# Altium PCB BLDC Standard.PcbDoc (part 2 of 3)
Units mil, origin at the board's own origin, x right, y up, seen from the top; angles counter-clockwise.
Board outline 4950 x 3000 mil, 4 copper layers (Top Layer, MidLayer1, MidLayer2, Bottom Layer), stack 63.4 mil thick; 211 components, 117 nets, 576 pads, 1027 vias.
Unrouted connection lines stored in the file: 2.
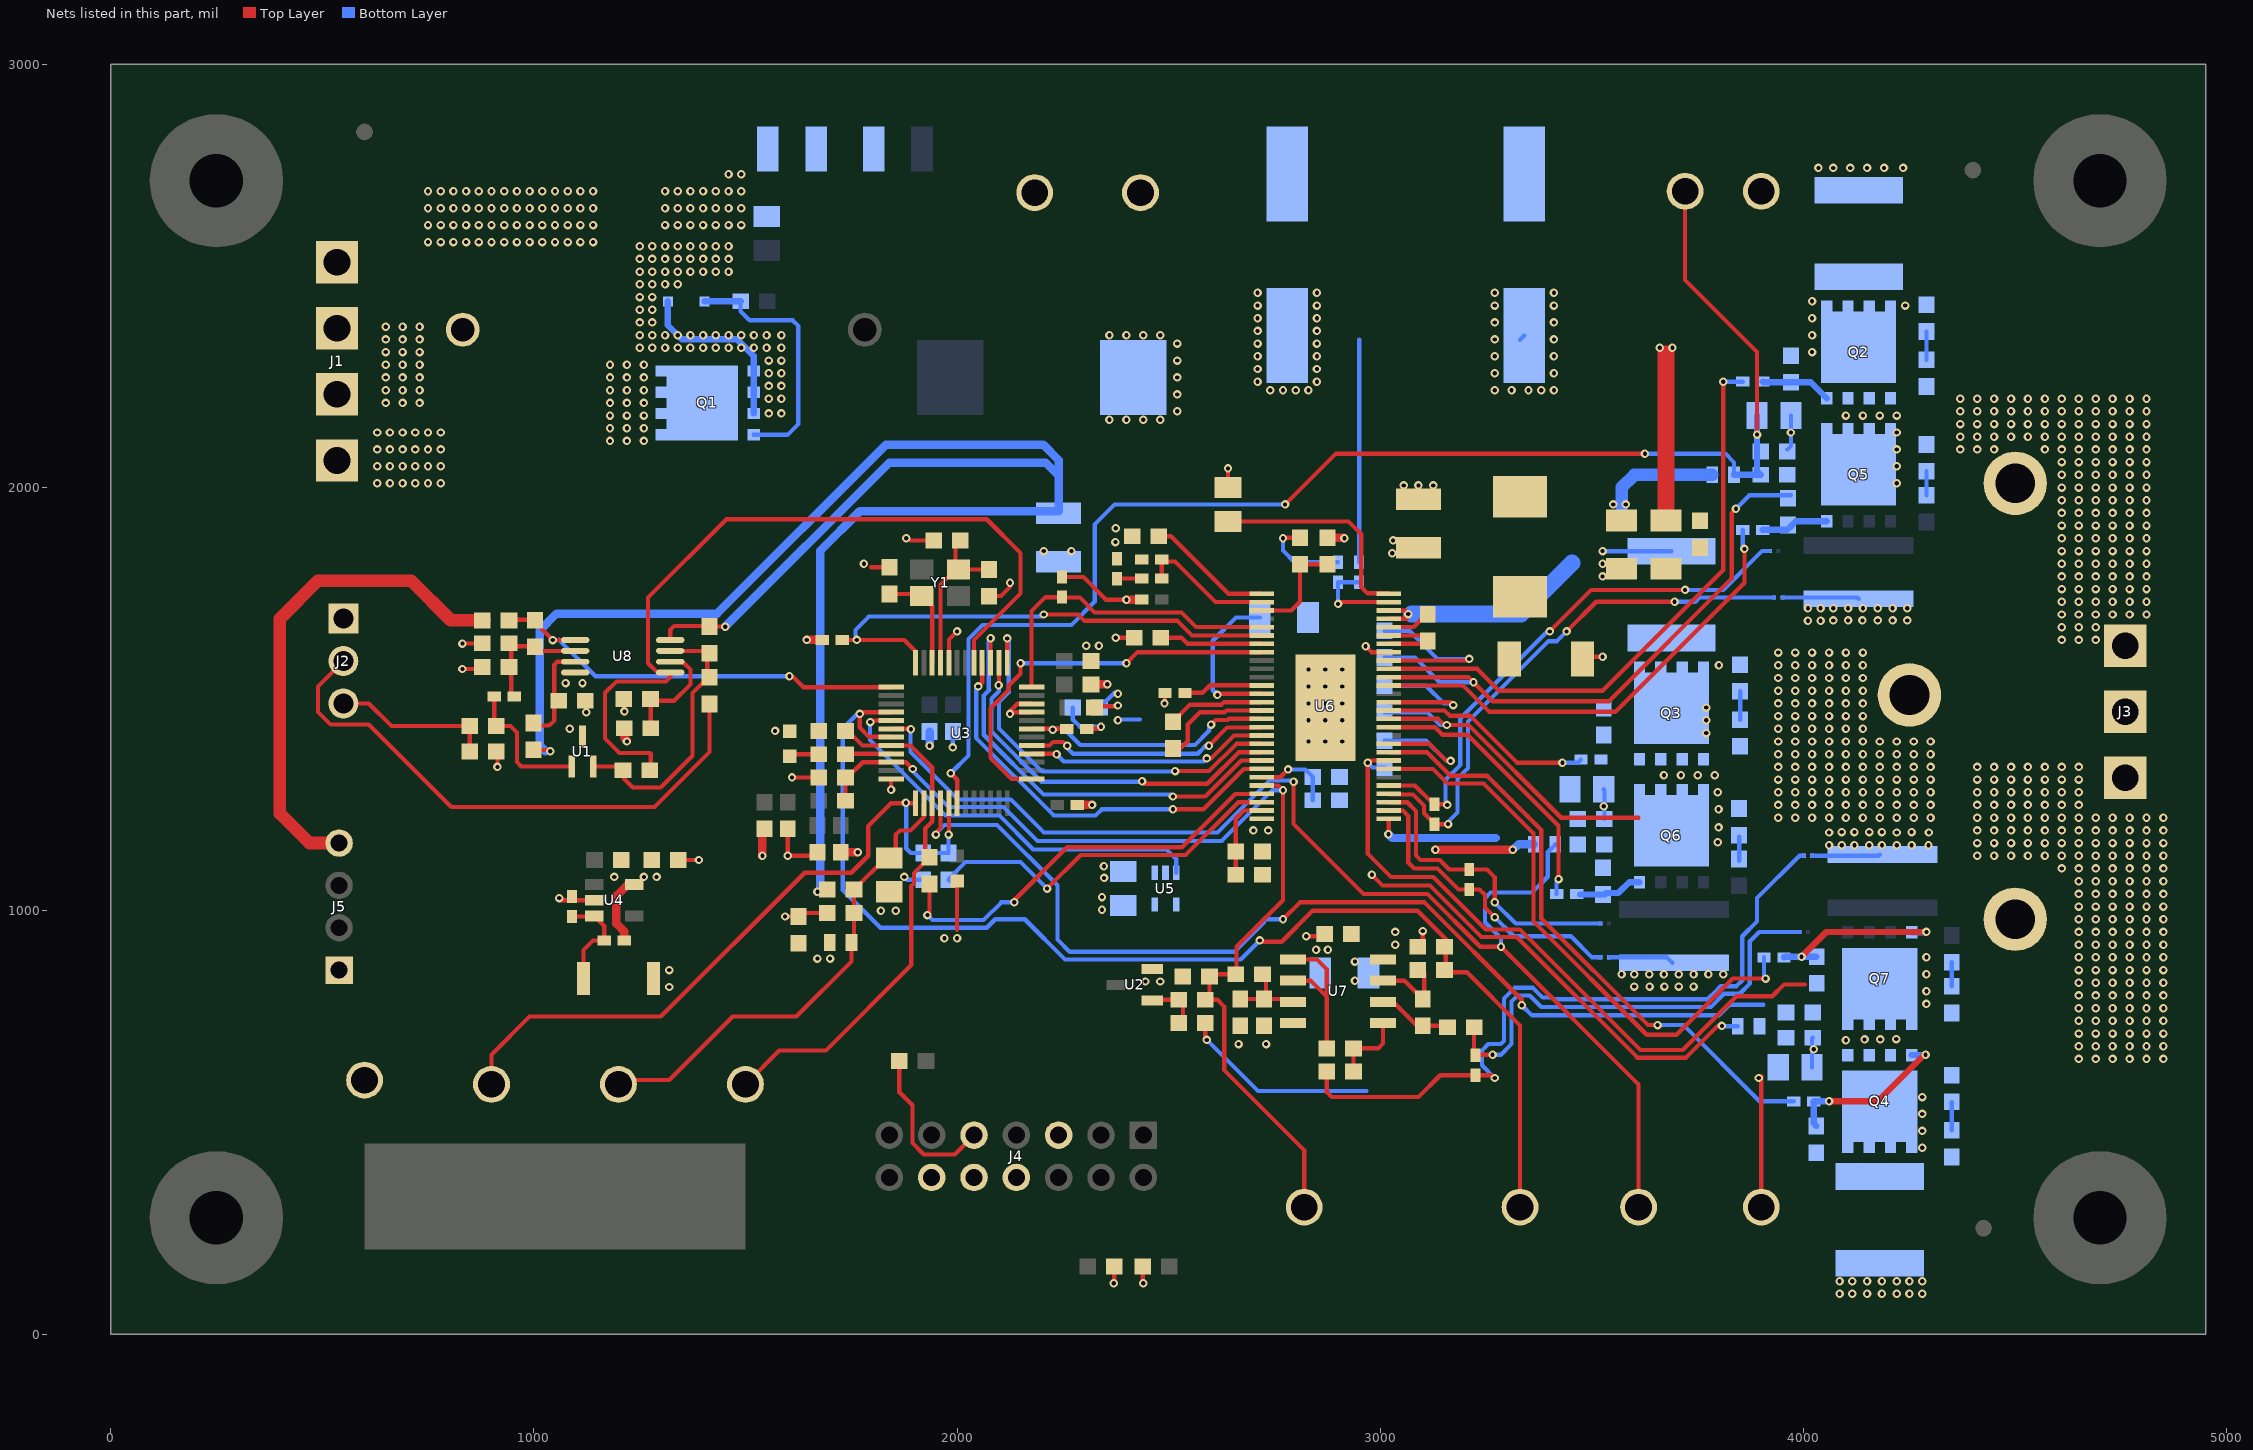
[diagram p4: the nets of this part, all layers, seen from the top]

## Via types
v1: diameter 20, hole 10, Top Layer to Bottom Layer, 1027 vias

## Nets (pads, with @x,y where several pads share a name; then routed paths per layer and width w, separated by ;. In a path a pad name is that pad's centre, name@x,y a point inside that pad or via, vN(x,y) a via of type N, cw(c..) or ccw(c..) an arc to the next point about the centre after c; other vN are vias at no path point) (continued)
3P3V: C30.2 C36.1 C38.1 C45.1 C46.1 C61.2 D2.1 D3.1 D4.1 D5.1 J4.5 J5.4 L2.1 L3.1 L4.1 L5.1 L7.2 R2.2 R12.2 R45.2 R47.2 R52.1 R53.2 R54.1 R58.2 R59.1 U4.5 U5.4 U5.5 U6.49 U7.8 | length 3510.6
  Top Layer w10: R52.1@2248,1788.62 2298.38,1788.62 2352,1735 v1(2400,1735) ; v1(2965,1625) 2978.89,1611.11 U6.49@3019.92,1611.11 ; v1(2980,1085) 3005,1060 3117,1060 3239,938 3322.09,938 3607.09,653 3721.89,653 3796.89,728 v1(3807,728)
  Top Layer w20: R12.2@1213.5,1431.3 1213.5,1409.5 v1@1220,1403 ; R47.2@1213.62,930 1213.62,951.38 1208.2,956.8 1208.13,956.8 1195,969.94 1195,1035.16 1222.24,1062.4 U4.5@1237.24,1062.4 ; v1(1540,1130) L2.1@1540,1178.5 ; v1(1645,1640) R54.1@1681.38,1640 ; L5.1@1725,1138.5 v1(1765.5,1138.5) ; R59.1@2283.62,1250 v1@2315,1250 ; L4.1@2316.5,1535 v1(2355,1535) ; v1(2400,1735) R58.2@2436.38,1735 ; R53.2@2875,1881.5 2913.5,1881.5 v1(2915,1880) ; v1(3130,1144) v1(3312.63,1144)
  Top Layer w30: J5.4@540,1160 470,1160 400,1230 400,1690 490,1780 710,1780 803.7,1686.3 R2.2@883.5,1686.3
  Bottom Layer w10: v1(3807,728) 3808,727 D4.1@3844.41,727
  Bottom Layer w20: v1(1935,1390) L3.1@1935,1423.5 ; v1(3312.63,1144) 3326.94,1157 ; 3326.97,1156.97 D3.1@3362.2,1156.97
  Bottom Layer w30: 3570,1955 3570,2000 3600,2030 D2.1@3784.41,2030
  other v1: 1670,887 1700,887 3035,920 3035,950 2342.32,1002.56 2342.32,1032.56 1190,1080 1260,1080 1290,1080 2319,1250 1220,1400 3028.28,1845 3030,1875 3550,1960 3580,1960
A_H_ISENSE: C64.1 NT1.2 U6.33 | length 1257.8
  Top Layer w10: U6.33@3019.92,1295.91 3081.37,1295.91 C64.1@3123,1254.28 ; C64.1@3123,1251.62 3123,1251 3126.46,1251 C64.1@3129,1253.54 ; C64.1@3129,1251.62 3153.38,1251.62 v1@3155,1250 ; v1(3400,1660) 3498,1758 v1(3720,1758)
  Bottom Layer w10: v1@3154,1250 3154,1309.46 3189,1344.46 3189,1454.81 3390.64,1656.46 ; v1(3720,1758) 3810,1758 3902,1850 NT1.2@3920,1850
  other v1: 3158,1250
A_I_ADC: C60.1 R63.2 TP10.1 U3.8 U3.15 | length 1250.5
  Top Layer w10: TP10.1@1500,590 1580,670 1690,670 1891.85,871.85 1891.85,1058.18 1898,1064.33 1898,1089.5 R63.2@1925,1116.5 ; C60.1@1736.5,1425 1742,1425 1776.5,1390.5 U3.8@1844.1,1390.5 1889.5,1390.5 1941.2,1338.8 U3.15@1941.2,1254 1941.2,1211.2 1925,1195 R63.2@1925,1116.5 ; R63.2@1935,1126.5 R63.2@1925,1116.5
A_L_ISENSE: C64.2 NT4.2 U6.32 | length 1283.8
  Top Layer w10: U6.32@3019.92,1276.21 3021.12,1275.01 3076.81,1275.01 3103,1248.82 3103,1230.38 3129,1204.38 3154.38,1204.38 v1@3155,1205 ; v1(3440,1660) 3510,1730 v1(3695,1730)
  Bottom Layer w10: v1@3155,1205 3182,1232 3182,1312 3207,1337 3207,1447 3397,1637 3417,1637 v1(3440,1660) ; v1(3695,1730) 3744,1730 3754,1740 NT4.2@3930,1740
  other v1: 3160,1205
A_PHASE: C14.2 C20.1 C47.2 J3.1 PTH-A.1 Q2.1 Q2.2 Q2.3 Q5.5 Q5.6 Q5.7 Q5.8 Q5.9 R21.1 R27.1 U6.46 | length 1493.2
  Top Layer w10: U6.46@3019.92,1552.01 3207.99,1552.01 v1@3215,1545 ; v1(3220,1540) 3265,1495 3540,1495 3830,1785 3830,1940 v1(3840,1950)
  Bottom Layer w10: C47.2@3010,1598.5 3081.5,1598.5 3140,1540 v1(3220,1540) ; v1(3840,1950) 3871.5,1981.5 C20.1@3970,1981.5
  other v1: 4610,1640 4650,1640 4690,1640 4610,1670 4650,1670 4690,1670 4610,1700 4650,1700 4690,1700 4730,1700 4770,1700 4810,1700 4610,1730 4650,1730 4690,1730 4730,1730 4770,1730 4810,1730 4610,1760 4650,1760 4690,1760 4730,1760 4770,1760 4810,1760 4610,1790 4650,1790 4690,1790 4730,1790 4770,1790 4810,1790 4610,1820 4650,1820 4690,1820 4730,1820 4770,1820 4810,1820 4610,1850 4650,1850 4690,1850 4730,1850 4770,1850 4810,1850 4610,1880 4650,1880 4690,1880 4730,1880 4770,1880 4810,1880 4610,1910 4650,1910 4690,1910 4730,1910 4770,1910 4810,1910 4610,1940 4650,1940 4690,1940 4730,1940 4770,1940 4810,1940 4610,1970 4650,1970 4690,1970 4730,1970 4770,1970 4810,1970 4610,2000 4650,2000 4690,2000 4730,2000 4770,2000 4810,2000 4220,2010 4610,2030 4650,2030 4690,2030 4730,2030 4770,2030 4810,2030 4220,2050 4610,2060 4650,2060 4690,2060 4730,2060 4770,2060 4810,2060 4220,2090 4370,2090 4410,2090 4450,2090 4570,2090 4610,2090 4650,2090 4690,2090 4730,2090 4770,2090 4810,2090 4370,2120 4410,2120 4450,2120 4490,2120 4530,2120 4570,2120 4610,2120 4650,2120 4690,2120 4730,2120 4770,2120 4810,2120 4220,2130 4370,2150 4410,2150 4450,2150 4490,2150 4530,2150 4570,2150 4610,2150 4650,2150 4690,2150 4730,2150 4770,2150 4810,2150 4100,2170 4140,2170 4180,2170 4220,2170 4370,2180 4410,2180 4450,2180 4490,2180 4530,2180 4570,2180 4610,2180 4650,2180 4690,2180 4730,2180 4770,2180 4810,2180 4370,2210 4410,2210 4450,2210 4490,2210 4530,2210 4570,2210 4610,2210 4650,2210 4690,2210 4730,2210 4770,2210 4810,2210
A_V_ADC: C17.1 D2.2 R21.2 R24.2 TP9.1 U3.18 | length 3398.7
  Top Layer w10: v1(1985,1325) 2000.3,1309.7 U3.18@2000.3,1254 ; v1(2775,1960) 2895,2080 v1(3625,2080) ; TP9.1@3720,2700 3720,2490 3890,2320 v1(3890,2125)
  Bottom Layer w10: v1(1985,1325) 2027,1367 2027,1642 2060,1675 2270,1675 2325,1730 2325,1913 2372,1960 v1(2775,1960) ; v1(3625,2080) 3815,2080 3835.59,2059.41 D2.2@3835.59,2030
  Bottom Layer w15: D2.2@3835.59,2030 R21.2@3898.5,2030 3890,2038.5 C17.1@3890,2170
ADC_REF: C29.1 C54.1 R36.2 R38.2 R65.2 TP5.1 U3.10 U6.24 | length 2491.5
  Top Layer w10: R36.2@1736.5,1260 C54.1@1736.5,1315 1741,1315 1777.1,1351.1 U3.10@1844.1,1351.1 1878.9,1351.1 v1(1895,1335) ; R38.2@2586.5,790 R38.2@2596.5,790 ; U6.24@2719.92,1295.91 2759.09,1295.91 v1(2770,1285) 2770,1025 2660,915 2660,851.5 R65.2@2658.5,850 2601.5,850 C29.1@2596.5,845 R38.2@2596.5,790 ; TP5.1@2820,300 2820,435 2631,624 2631,774 2615,790 R38.2@2596.5,790
  Bottom Layer w10: v1(1895,1335) 1895,1330 1980,1245 2110,1245 2190,1165 2625,1165 2745,1285 v1(2770,1285)
AH_GATE: R18.1 U6.47 | length 1420.9
  Top Layer w10: U6.47@3019.92,1571.71 3228.29,1571.71 3280,1520 3525,1520 3810,1805 v1(3810,2250)
  Bottom Layer w10: v1(3810,2250) R18.1@3856.38,2250
AH_PWM: U3.29 U6.17 | length 587.9
  Top Layer w10: U3.29@2176.1,1390.5 2218.5,1390.5 2227,1399 2251,1399 v1(2260,1390) ; v1(2595,1390) 2638,1433 2719.11,1433 U6.17@2719.92,1433.81
  Bottom Layer w10: v1(2260,1390) 2260,1385 2274,1371 2568.47,1371 2582.48,1385 2587.47,1390 v1(2595,1390)
AL_GATE: R30.1 U6.45 | length 1118.7
  Top Layer w10: U6.45@3019.92,1532.31 3195.16,1532.31 3257.47,1470 3555,1470 3860,1775 v1(3860,1855)
  Bottom Layer w10: R30.1@3856.38,1900 3856.38,1858.62 v1(3860,1855)
AL_PWM: U3.28 U6.18 | length 576.5
  Top Layer w10: U3.28@2176.1,1370.8 2234.2,1370.8 v1(2235,1370) ; v1(2590,1360) 2600,1360 2654.11,1414.11 U6.18@2719.92,1414.11
  Bottom Layer w10: v1(2235,1370) 2252,1353 2583,1353 v1(2590,1360)
B_H_ISENSE: C65.1 NT2.2 U6.31 | length 715.4
  Top Layer w10: U6.31@3019.92,1256.51 3063.49,1256.51 3084,1236 3084,1131 3095,1120 3140.46,1120 3162.76,1097.7 C65.1@3210,1097.7 3252.3,1097.7 3270,1080 v1(3270,1020)
  Bottom Layer w10: v1(3270,1020) 3320,970 NT2.2@3520,970
B_I_ADC: C59.1 R62.2 TP8.1 U3.13 U3.17 | length 1689
  Top Layer w10: TP8.1@900,590 900,660 990,750 1300,750 1640,1090 1750,1090 1790,1130 1790,1200 1844,1254 U3.13@1901.8,1254 ; v1(1980,1180) 1980.6,1180.6 U3.17@1980.6,1254
  Bottom Layer w10: v1@1880,1255 1880,1147 1890.5,1136.5 C59.1@1920,1136.5 R62.2@1980,1136.5 v1(1980,1180)
  other v1: 1879,1255
B_L_ISENSE: C65.2 NT5.2 U6.30 | length 725.8
  Top Layer w10: U6.30@3019.92,1236.83 3053.17,1236.83 3066,1224 3066,1114 3080,1100 3135,1100 3184.54,1050.46 C65.2@3210,1050.46 3234.54,1050.46 3247,1038 3247,1009.97 3247.5,1009.47 3247.5,1007.5 v1(3270,985)
  Bottom Layer w10: v1(3270,985) 3315,940 3450,940 3500,890 NT5.2@3520,890
B_PHASE: C15.2 C21.1 C49.2 J3.2 PTH-B.1 Q3.1 Q3.2 Q3.3 Q6.5 Q6.6 Q6.7 Q6.8 Q6.9 R22.1 R28.1 U6.41 | length 840
  Top Layer w10: U6.41@3019.92,1453.51 3136.49,1453.51 v1@3150,1440 ; v1(3157,1439) 3208.37,1439 3427.37,1220 3610,1220
  Bottom Layer w10: C49.2@3010,1468.5 3111.5,1468.5 3141,1439 v1@3149,1439 ; v1@3150,1440 v1@3149,1439 ; v1(3157,1439) v1@3149,1439
  other v1: 3797,1162 3799,1197 3940,1220 3980,1220 4020,1220 4060,1220 4100,1220 4140,1220 4180,1220 4220,1220 4260,1220 4300,1220 3799,1240 3940,1250 3980,1250 4020,1250 4060,1250 4100,1250 4140,1250 4180,1250 4220,1250 4260,1250 4300,1250 3797,1280 3940,1280 3980,1280 4020,1280 4060,1280 4100,1280 4140,1280 4180,1280 4220,1280 4260,1280 4300,1280 3940,1310 3980,1310 4020,1310 4060,1310 4100,1310 4140,1310 4180,1310 4220,1310 4260,1310 4300,1310 3670,1320 3710,1320 3750,1320 3790,1320 3940,1340 3980,1340 4020,1340 4060,1340 4100,1340 4140,1340 4180,1340 4220,1340 4260,1340 4300,1340 3940,1370 3980,1370 4020,1370 4060,1370 4100,1370 4140,1370 4180,1370 4220,1370 4260,1370 4300,1370 3940,1400 3980,1400 4020,1400 4060,1400 4100,1400 4140,1400 4180,1400 4220,1400 4260,1400 4300,1400 3940,1430 3980,1430 4020,1430 4060,1430 4100,1430 4140,1430 3940,1460 3980,1460 4020,1460 4060,1460 4100,1460 4140,1460 3940,1490 3980,1490 4020,1490 4060,1490 4100,1490 4140,1490 3940,1520 3980,1520 4020,1520 4060,1520 4100,1520 4140,1520 3940,1550 3980,1550 4020,1550 4060,1550 4100,1550 4140,1550 3940,1580 3980,1580 4020,1580 4060,1580 4100,1580 4140,1580 3940,1610 3980,1610 4020,1610 4060,1610 4100,1610 4140,1610
B_V_ADC: C18.1 D3.2 R22.2 R25.2 TP7.1 U3.6 | length 2980.1
  Top Layer w10: U3.6@1844.1,1429.9 v1@1889.9,1429.9 ; v1(2795,1305) 2795,1205 2960,1040 3111,1040 3236,915 v1(3285,915) 3610,590 TP7.1@3610,300
  Bottom Layer w10: v1@1889.9,1429.9 1889.9,1375.1 2002,1263 2127,1263 2205,1185 2615,1185 2738,1308 2792,1308 v1(2795,1305) ; v1(3285,915) 3285,935 3247,973 3247,1029.53 3260.47,1043 3358,1043 3395.51,1080.51 3395.51,1139.09 D3.2@3413.39,1156.97
  other v1: 1891,1429
BATT_GND: C5.2 C6.2 J1.1 J1.4 Q1.5 Q1.6 Q1.7 Q1.8 Q1.9
  other v1: 630,2010 660,2010 690,2010 720,2010 750,2010 780,2010 630,2050 660,2050 690,2050 720,2050 750,2050 780,2050 630,2090 660,2090 690,2090 720,2090 750,2090 780,2090 1180,2110 1220,2110 1260,2110 630,2130 660,2130 690,2130 720,2130 750,2130 780,2130 1180,2140 1220,2140 1260,2140 1180,2170 1220,2170 1260,2170 1180,2200 1220,2200 1260,2200 1180,2230 1220,2230 1260,2230 1180,2260 1220,2260 1260,2260 1180,2290 1220,2290 1260,2290 750,2580 780,2580 810,2580 840,2580 870,2580 900,2580 930,2580 960,2580 990,2580 1020,2580 1050,2580 1080,2580 1110,2580 1140,2580 750,2620 780,2620 810,2620 840,2620 870,2620 900,2620 930,2620 960,2620 990,2620 1020,2620 1050,2620 1080,2620 1110,2620 1140,2620 1310,2620 1340,2620 1370,2620 1400,2620 1430,2620 1460,2620 1490,2620 750,2660 780,2660 810,2660 840,2660 870,2660 900,2660 930,2660 960,2660 990,2660 1020,2660 1050,2660 1080,2660 1110,2660 1140,2660 1310,2660 1340,2660 1370,2660 1400,2660 1430,2660 1460,2660 1490,2660 750,2700 780,2700 810,2700 840,2700 870,2700 900,2700 930,2700 960,2700 990,2700 1020,2700 1050,2700 1080,2700 1110,2700 1140,2700 1310,2700 1340,2700 1370,2700 1400,2700 1430,2700 1460,2700 1490,2700 1460,2740 1490,2740
BH_GATE: R19.1 U6.42 | length 508.2
  Top Layer w10: U6.42@3019.92,1473.21 3151.79,1473.21 3164,1461 3211.82,1461 3322.82,1350 v1(3430,1350)
  Bottom Layer w10: v1(3430,1350) 3467.2,1350 R19.1@3474.17,1356.97
BH_PWM: U3.37 U6.19 | length 971.2
  Top Layer w10: U3.37@2118.5,1585.9 v1(2118.5,1643.5) ; v1(2515,1330) 2595.46,1330 2659.87,1394.41 U6.19@2719.92,1394.41
  Bottom Layer w10: v1(2118.5,1643.5) 2121.8,1640.2 2121.8,1516.34 2099,1493.54 2099,1431 2201,1329 2514,1329 v1(2515,1330)
BL_GATE: R31.1 U6.40 | length 660.4
  Top Layer w10: U6.40@3019.92,1433.81 3129.19,1433.81 3147,1416 3205.91,1416 3421,1200.91 v1(3421,1075)
  Bottom Layer w10: R31.1@3416.38,1040 3416.38,1070.38 v1(3421,1075)
BL_PWM: U3.38 U6.20 | length 892.6
  Top Layer w10: U3.38@2098.8,1585.9 2098.8,1531.2 v1@2100,1530 ; v1(2437,1306) 2443,1300 2590.91,1300 2665.62,1374.71 U6.20@2719.92,1374.71
  Bottom Layer w10: v1@2098.8,1531.2 2098.8,1518.8 2081,1501 2081,1423.54 2199.54,1305 2436,1305 v1@2436.5,1305.5
  other v1: 2098,1533
C_H_ISENSE: C66.2 NT3.2 R70.1 | length 1093.4
  Top Layer w10: R70.1@3221.5,725 3221.5,662.13 C66.2@3225,658.62 3226.38,660 v1(3265,660)
  Bottom Layer w10: v1(3265,660) 3285,660 3310,685 3310,785.53 3324.47,800 3353,800 3380,773 3780.98,773 3811.98,804 3849,804 3872.96,827.96 3872.96,927.96 3895,950 NT3.2@3990,950
C_I_ADC: C62.1 R64.2 TP12.1 U3.4 U3.7 | length 2943.3
  Top Layer w10: v1(1770,1465) 1770,1433 1792.01,1410.99 1843.3,1410.99 U3.7@1844.1,1410.2 ; v1@1774.3,1469.3 U3.4@1844.1,1469.3 ; v1(2715,930) 2718,927 2767,927 2840,1000 3088,1000 3154.45,933.55 3154.45,855 3204,855 3330,729 TP12.1@3330,300
  Bottom Layer w10: v1(1770,1465) 1764,1465 1730,1431 1730,1049 1819,960 2070,960 2090,980 2160,980 2255,885 2670,885 v1(2715,930)
C_L_ISENSE: C66.1 NT6.2 R69.1 | length 1676.7
  Top Layer w10: R69.1@2873.5,620 2873.5,571.5 2885,560 3090,560 3141.38,611.38 C66.1@3225,611.38 3263.62,611.38 v1(3270,605)
  Bottom Layer w10: v1(3270,605) 3240,635 3240,670 3255,685 3284.54,685 3292,692.46 3292,792.98 3317.02,818 3360.46,818 3383.46,795 3405.46,795 3409.46,791 3773.53,791 3798,815.47 3798,816 3804,822 3841.54,822 3854.96,835.42 3854.96,939.96 3890,975 3890,1030 3990,1130 NT6.2@4000,1130
C_PHASE: C16.2 C22.1 C51.2 J3.3 PTH-C.1 Q4.1 Q4.2 Q4.3 Q7.5 Q7.6 Q7.7 Q7.8 Q7.9 R23.1 R29.1 U6.36 | length 1601
  Top Layer w10: U6.36@3019.92,1355.01 2975.01,1355.01 v1(2970,1350) 2970,1135 3025,1080 3125,1080 3249,956 3329.54,956 3614.54,671 3714.44,671 3841.42,797.98 3925.96,797.98 3953.98,826 4002.8,826
  Bottom Layer w10: v1(2970,1350) 2981.5,1338.5 C51.2@3010,1338.5
  other v1: 4650,650 4690,650 4730,650 4770,650 4810,650 4850,650 4650,680 4690,680 4730,680 4770,680 4810,680 4850,680 4100,694 4144,696 4181,696 4219,697 4650,710 4690,710 4730,710 4770,710 4810,710 4850,710 4650,740 4690,740 4730,740 4770,740 4810,740 4850,740 4650,770 4690,770 4730,770 4770,770 4810,770 4850,770 4290,780 4650,800 4690,800 4730,800 4770,800 4810,800 4850,800 4290,810 4650,830 4690,830 4730,830 4770,830 4810,830 4850,830 4290,850 4650,860 4690,860 4730,860 4770,860 4810,860 4850,860 4290,890 4650,890 4690,890 4730,890 4770,890 4810,890 4850,890 4650,920 4690,920 4730,920 4770,920 4810,920 4850,920 4650,950 4690,950 4730,950 4770,950 4810,950 4850,950 4650,980 4690,980 4730,980 4770,980 4810,980 4850,980 4650,1010 4690,1010 4730,1010 4770,1010 4810,1010 4850,1010 4650,1040 4690,1040 4730,1040 4770,1040 4810,1040 4850,1040 4650,1070 4690,1070 4730,1070 4770,1070 4810,1070 4850,1070 4610,1100 4650,1100 4690,1100 4730,1100 4770,1100 4810,1100 4850,1100 4410,1130 4450,1130 4490,1130 4530,1130 4570,1130 4610,1130 4650,1130 4690,1130 4730,1130 4770,1130 4810,1130 4850,1130 4410,1160 4450,1160 4490,1160 4530,1160 4570,1160 4610,1160 4650,1160 4690,1160 4730,1160 4770,1160 4810,1160 4850,1160 4410,1190 4450,1190 4490,1190 4530,1190 4570,1190 4610,1190 4650,1190 4690,1190 4730,1190 4770,1190 4810,1190 4850,1190 4410,1220 4450,1220 4490,1220 4530,1220 4570,1220 4610,1220 4650,1220 4690,1220 4730,1220 4770,1220 4810,1220 4850,1220 4410,1250 4450,1250 4490,1250 4530,1250 4570,1250 4610,1250 4650,1250 4410,1280 4450,1280 4490,1280 4530,1280 4570,1280 4610,1280 4650,1280 4410,1310 4450,1310 4490,1310 4530,1310 4570,1310 4610,1310 4650,1310 4410,1340 4450,1340 4490,1340 4530,1340 4570,1340 4610,1340 4650,1340
C_V_ADC: C19.1 D4.2 R23.2 R26.2 TP11.1 U3.16 | length 2734.5
  Top Layer w10: v1@1950,1185 1960.9,1195.9 U3.16@1960.9,1254 ; v1(2770,980) 2810,1020 3104,1020 3334,790 v1(3334,777) ; TP11.1@3900,300 v1@3900,610
  Bottom Layer w10: v1@1945,1180 1947.47,1180 1970.47,1203 2094.53,1203 2237,1060.53 2237,932 2266,903 2655.47,903 2725,972.53 2725,980 v1(2770,980) ; v1(3334,777) 3358,753 3800,753 3825.2,778.2 3905.43,778.2
  other v1: 3894,605 1950,1180
CH_GATE: R20.1 U6.37 | length 1415.5
  Top Layer w10: U6.37@3019.92,1374.71 3110.2,1374.71 3165.96,1318.96 3252.04,1318.96 3380,1191 3380,981.91 3631.91,730 v1@3650,730
  Bottom Layer w10: v1(3655,730) 3716,730 3896,550 R20.1@3976.38,550
CH_PWM: U3.39 U6.21 | length 1046.4
  Top Layer w10: U3.39@2079.1,1585.9 v1(2079.1,1644.1) ; v1(2510,1270) 2586.37,1270 2671.38,1355.01 U6.21@2719.92,1355.01
  Bottom Layer w10: v1(2079.1,1644.1) 2075,1640 2075,1522.47 2076.01,1521.46 2063,1508.46 2063,1416.09 2204.09,1275 2505,1275 v1(2510,1270)
CL_GATE: R32.1 U6.35 | length 1379.1
  Top Layer w10: U6.35@3019.92,1335.31 3124.15,1335.31 3158.5,1300.96 3244.04,1300.96 3362,1183 3362,974.46 3629.46,707 3699.53,707 3832.53,840 v1(3910,840)
  Bottom Layer w10: R32.1@3906.38,890 3906.38,843.62 v1(3910,840)
CL_PWM: U3.40 U6.22 | length 984.9
  Top Layer w10: v1(2050,1530) 2059.4,1539.4 U3.40@2059.4,1585.9 ; v1(2510,1240) 2581.82,1240 2677.13,1335.31 U6.22@2719.92,1335.31
  Bottom Layer w10: v1(2050,1530) 2045,1525 2045,1408.63 2228.63,1225 2327,1225 2342,1240 v1(2510,1240) v1@2515,1240
DC+: C1.1 C3.1 C4.1 C8.1 C9.1 C10.1 C11.1 C12.1 C13.1 C40.1 C41.1 C57.1 C58.1 L1.2 Q2.5 Q2.6 Q2.7 Q2.8 Q2.9 Q3.5 Q3.6 Q3.7 Q3.8 Q3.9 Q4.5 Q4.6 Q4.7 Q4.8 Q4.9 R4.2 R9.2 R11.2 R15.1 R16.1 R17.1 R37.2 R39.1 R48.2 TP1.1 U6.29 U6.53 U6.54 U8.8 | length 6643.6
  Top Layer w10: R4.2@911.5,1376.3 914,1373.8 v1(914,1340) ; R9.2@1000,1379.8 1036.2,1379.8 v1(1039,1377) ; U8.8@1322.2,1639.69 1322.2,1663.5 1331.5,1672.8 R11.2@1410,1672.8 ; R11.2@1415,1671.5 1451.5,1671.5 v1(1452,1671) ; R37.2@2586.5,735 2586.5,698.5 v1(2590,695) ; v1(3019,1181) 3019.92,1181.92 U6.29@3019.92,1217.14 ; U6.53@3019.92,1689.91 3062.91,1689.91 ; U6.54@3019.92,1708.61 v1@3060,1708.61
  Top Layer w40: C40.1@3675,1922.09 3675,2315
  Bottom Layer w10: v1(2590,695) 2711,574 2967,574 ; R48.2@2950,1823.62 2950,2349.06 ; C1.1@3330,2349.06 C1.1@3340,2359.06
  Bottom Layer w20: 1027.27,1377.3 1014,1390.57 1014,1662 1054,1702 1433,1702 1832,2101 2204,2101 2240,2065 2240,2028 ; v1(1452,1671) 1840,2059 2209,2059 2240,2028 ; v1(1670,1045) 1677,1052 1677,1851 1770,1944 2240,1944 2240,2028 ; v1(3019,1181) 3028,1172 3273,1172
  Bottom Layer w40: v1@3074,1701 3332,1701 3453,1822
  other v1: 4280,440 4280,480 4280,520 4280,560 2940,835 2940,880 3770,1420 3770,1450 3770,1480 3800,1580 3066,1701 2360,2160 2400,2160 2440,2160 2480,2160 2520,2180 2520,2220 2740,2230 2770,2230 2800,2230 2830,2230 3270,2230 3310,2230 3350,2230 3380,2230 3410,2230 2710,2250 2850,2250 2520,2260 3270,2270 3410,2270 2710,2280 2850,2280 2520,2300 2710,2310 2850,2310 3270,2310 3410,2310 4019.96,2320 3660,2330 3690,2330 2520,2340 2710,2340 2850,2340 3270,2350 3410,2350 2360,2360 2400,2360 2440,2360 2480,2360 4020,2360 2710,2370 2850,2370 3270,2390 3410,2390 2710,2400 2850,2400 4020,2400 2710,2430 2850,2430 3270,2430 3410,2430 4240,2430 4020,2440 2710,2460 2850,2460 3270,2460 3410,2460
DC_V_ADC: C33.1 D5.2 R39.2 R40.2 TP6.1 U3.14 | length 1139.4
  Top Layer w10: TP6.1@1200,600 1320,600 1470,750 1620,750 1750.59,880.59 D5.2@1750.59,925 1756.5,930.91 R40.2@1756.5,995 R39.2@1756.5,1050 1831.5,1125 1855,1125 1855,1180 1865,1190 1890,1190 1921.5,1221.5 U3.14@1921.5,1254
DGND: C27.2 C28.2 C31.2 L6.2 U3.33 U3.34 U3.44 | length 353
  Top Layer w10: U3.44@1980.6,1585.9 1980.6,1640.6 v1(2000,1660) ; U3.33@2176.1,1469.3 2122.3,1469.3 2142,1489 U3.34@2176.1,1489 ; C28.2@2321.5,1480 2324.5,1483 2378,1483 v1(2380,1485)
  Bottom Layer w10: v1@1990,1389 C27.2@1990,1423.5 ; L6.2@2336.5,1480 2371.5,1515 2375,1515 v1@2380,1510
  other v1: 1990,1386 2125,1465 2380,1513 2305,1626 2335,1626
DRV_COMP: C42.1 R50.2 U6.2 | length 323
  Top Layer w10: R50.2@2483.62,1785 C42.1@2483.62,1830 2488.62,1825 2515,1825 2610.7,1729.3 U6.2@2719.92,1729.3
DRV_RT_CLK: R49.2 U6.1 | length 299.8
  Top Layer w10: R49.2@2476.5,1885 2505,1885 2641.02,1748.98 U6.1@2719.92,1748.98
DRV_SS_TR: C39.2 U6.56 | length 524
  Top Layer w10: C39.2@2640,1920 2925,1920 2955,1890 2955,1765 2970,1750 3018.9,1750 U6.56@3019.92,1748.98
DRV_VSENSE: R53.1 R55.2 U6.3 | length 252
  Top Layer w10: U6.3@2719.92,1709.61 2789.61,1709.61 2810,1730 R55.2@2810,1818.5 R53.1@2875,1818.5
EN_GATE: R61.2 U3.31 U6.16 | length 624.6
  Top Layer w10: U3.31@2176.1,1429.9 2258.48,1429.9 R61.2@2259.38,1429 ; v1(2600,1440) 2611,1451 2639.44,1451 2641.95,1453.51 U6.16@2719.92,1453.51
  Bottom Layer w10: v1@2226,1430 2253,1430 2291,1392 2562,1392 2595.68,1425.68 2595.68,1435.68 v1(2600,1440)
  other v1: 2226,1428
FAULT: R54.2 U3.48 U6.6 | length 1230.6
  Top Layer w10: R54.2@1728.62,1640 1760,1640 1875,1640 1901.8,1613.2 U3.48@1901.8,1585.9 ; v1(2205,1700) 2286,1700 2301,1685 2520.51,1685 2555,1650.51 U6.6@2719.92,1650.51
  Bottom Layer w10: v1@1760,1640 1760,1663.54 1791.46,1695 2200,1695 v1(2205,1700)
  other v1: 1763,1640
GND: C1.2 C3.2 C4.2 C7.2 C8.2 C9.2 C10.2 C17.2 C18.2 C19.2 C26.2 C29.2 C30.1 C32.2 C33.2 C34.2 C35.2 C36.2 C37.2 C38.2 C39.1 C40.2 C41.2 C42.2 C44.2 C45.2 C46.2 C48.2 C52.2 C53.2 C54.2 C55.2 C56.2 C57.2 C58.2 C59.2 C60.2 C61.1 C62.2 C63.2 D1.2 D6.2 D7.2 D8.2 J2.1 J4.8 J4.10 J4.12 J5.1 L6.1 NT4.1 NT5.1 NT6.1 Q1.1 Q1.2 Q1.3 R7.1 R10.2 R13.1 R24.1 R25.1 R26.1 R33.1 R34.1 R35.1 R40.1 R41.1 R46.1 R49.1 R51.1 R55.1 R56.1 R60.1 R61.1 R67.2 R71.2 S1.1 TP2.1 TP3.1 TP4.1 U1.3 U2.2 U3.12 U4.2 U5.1 U5.2 U6.28 U6.57 U7.4 U8.4 | length 2970.7
  Top Layer w10: v1(831.3,1571.3) C7.2@883.5,1571.3 ; v1(831.3,1631.3) R7.1@883.5,1631.3 ; v1(1060,1030) 1065,1025 U4.2@1142.76,1025 ; R13.1@1213.5,1496.3 1213.5,1466.5 v1@1215,1465 ; C36.2@1341.5,1120 v1(1390,1120) ; v1(1593.5,986.5) C30.1@1625,986.5 1633.5,995 R40.1@1693.5,995 ; C26.2@1600,1193.5 v1(1600,1130) 1661.5,1130 C32.2@1670,1138.5 ; v1(1610,1315) C54.2@1673.5,1315 ; 1796.5,1811.5 C35.2@1840,1811.5 ; U3.12@1844.1,1311.7 v1(1844.1,1285.9) v1@1845,1285 ; 1890,1875 C34.2@1933.5,1875 ; 2000,955 D6.2@2000,1070.47 ; R71.2@2075,1743.5 2103.5,1743.5 2125,1765 v1(2125,1775) ; R61.1@2298.62,1430 v1@2340,1430 ; v1(2370,120) 2371.5,121.5 R41.1@2371.5,160 ; v1(2375,1645) R56.1@2418.5,1645 ; R46.1@2438.5,160 2438.5,121.5 v1(2440,120) ; v1(2490,1490) 2491.38,1491.38 R60.1@2491.38,1515 ; C39.1@2640,2000 v1(2640,2045) ; v1(2770,1880) 2771.5,1881.5 R55.1@2810,1881.5 ; v1(2825,940) 2863.5,940 C61.1@2868.5,945 ; C62.2@3088.5,915 3100,926.5 v1(3100,952) ; D7.2@3476.61,1600 v1(3525,1600)
  Bottom Layer w10: v1(1875,1080) 1881.5,1073.5 C59.2@1920,1073.5 ; L6.1@2273.5,1480 2273.5,1451.5 2290,1435 2335,1435 v1@2340,1430 ; v1@2379,1452 2431.91,1452 ; v1(2770,1880) 2770,1851.46 2797.83,1823.62 R51.1@2900,1823.62 ; v1(3525,1850) 3525.67,1849.33 C9.2@3687.8,1849.33 ; C18.2@3527.8,1286.97 3529.29,1285.47 R25.1@3529.29,1216.97 ; NT5.1@3540,890 3677.01,890 R34.1@3690,877.01 ; NT4.1@3950,1740 4127.01,1740 R33.1@4130,1737.01 ; R24.1@3961.5,2090 3970,2098.5 C17.2@3970,2170 ; C19.2@4020,630 4020,698.5 R26.1@4021.5,700 ; NT6.1@4020,1130 4177.01,1130 R35.1@4180,1132.99
  Bottom Layer w15: D1.2@1316.69,2440 1316.69,2383.31 1350,2350 1480,2350 1519.3,2310.7 Q1.1@1519.3,2275.49 Q1.2@1519.3,2225.16 Q1.3@1519.3,2174.84
  other v1: 4085,95 4115,95 4150,95 4185,95 4220,95 4250,95 4280,95 4085,124.6 4115,124.6 4150,124.6 4185,125 4220,124.6 4250,124.6 4280,124.6 4024,672.8 2665,685 2730,685 1320,820 3600,821 3636,821 3671,821 3705,821 3740,821 2445,833 2480,833 3570,850 3600,850 3635,850 3670,850 3705,850 3740,850 3775,850 3810,850 1320,860 2848,908 2876,908 1970,935 2000,935 1820,1000 1855,1000 2347.32,1077.56 2347,1105 4060,1155 4090,1155 4120,1155 4155,1155 4185,1155 4220,1155 4255,1155 4295,1155 4060,1185 4220,1185 4296,1185 4090,1186 4120,1186 4155,1186 4185,1186 4255,1186 2700,1190 2735,1190 3527.8,1246.97 2830,1400 2870,1400 2910,1400 1570,1425 1085,1430 2340,1435 2380,1450 2830,1450 2870,1450 2910,1450 1124,1469.1 1214,1471 2830,1490 2870,1490 2910,1490 2830,1530 2870,1530 2910,1530 1075,1538 1115,1538 2830,1570 2870,1570 2910,1570 4010,1685 4040,1685 4070,1686 4105,1686 4139,1686 4175,1686 4210,1686 4245,1686 4010,1715 4040,1715 4070,1715 4105,1715 4140,1715 4175,1715 4210,1715 4245,1715 3525,1790 1780,1820 3525,1820 2205,1850 2270,1850 2374,1871 1880,1880 2375,1904 3055,2005 3090,2005 3125,2005 3970,2130 1555,2175 1585,2175 1555,2210 1585,2210 1555,2240 1585,2240 1555,2270 1585,2270 1555,2300 1585,2300 1250,2330 1280,2330 1310,2330 1340,2330 1370,2330 1400,2330 1430,2330 1460,2330 1490,2330 1520,2330 1550,2330 1585,2330 1250,2360 1280,2360 1310,2360 1340,2360 1370,2360 1400,2360 1430,2360 1460,2360 1490,2360 1520,2360 1550,2360 1585,2360 1250,2390 1280,2390 1250,2420 1280,2420 1250,2450 1280,2450 1250,2480 1280,2480 1310,2480 1340,2480 1250,2510 1280,2510 1310,2510 1340,2510 1370,2510 1400,2510 1430,2510 1460,2510 1250,2540 1280,2540 1310,2540 1340,2540 1370,2540 1400,2540 1430,2540 1460,2540 1250,2570 1280,2570 1310,2570 1340,2570 1370,2570 1400,2570 1430,2570 1460,2570 4035,2755 4070,2755 4110,2755 4150,2755 4190,2755 4235,2755
HALF_REF: C63.1 R65.1 R67.1 U7.3 | length 188.4
  Top Layer w10: C63.1@2670,791.5 R67.1@2730,791.5 ; R65.1@2721.5,850 2730,841.5 R67.1@2730,791.5 ; U7.3@2793.7,785 2787.2,791.5 R67.1@2730,791.5
IN_PWM: R2.1 R3.2 U3.1 U8.1 | length 1022.8
  Top Layer w10: R2.1@946.5,1686.3 947.99,1687.8 R3.2@1008,1687.8 ; R3.2@1003,1686.5 1003,1681.37 v1(1044.69,1639.69) U8.1@1097.8,1639.69 ; v1@1606,1553 1612,1553 1636.6,1528.4 U3.1@1844.1,1528.4
  Bottom Layer w10: v1(1044.69,1639.69) 1059.28,1639.69 1059.8,1640.2 1146,1554 v1(1604,1554)
NetC2_2: C2.2 C6.1
NetC7_1: C7.1 R3.1 R6.1 R7.2 U8.2 | length 272.8
  Top Layer w10: R6.1@953.62,1506.3 946.5,1513.43 946.5,1618.31 952.99,1624.8 R3.1@1003,1624.8 ; R3.1@1003,1623.5 1012.41,1614.09 U8.2@1097.8,1614.09
NetC11_2: C11.2 Q2.4 R18.2 | length 167.2
  Bottom Layer w15: R18.2@3903.62,2250 3905.12,2248.5 C11.2@3970,2248.5 4016.7,2248.5 Q2.4@4054.51,2210.7
NetC12_2: C12.2 Q3.4 R19.2
NetC13_2: C13.2 Q4.4 R20.2 | length 397.4
  Top Layer w15: v1(4060,550) 4175,550 v1@4285,660
  Bottom Layer w15: C13.2@4030,491.5 4023.62,497.87 R20.2@4023.62,550 v1(4060,550) ; Q4.4@4255.49,659.3 4283.8,659.3 v1@4284.5,660
  other v1: 4288,660
NetC14_1: C14.1 R15.2 | length 67
  Bottom Layer w10: C14.1@4290,2301.5 R15.2@4290,2368.5
NetC15_1: C15.1 R16.2 | length 67
  Bottom Layer w10: C15.1@3850,1451.5 R16.2@3850,1518.5
NetC16_1: C16.1 R17.2 | length 67
  Bottom Layer w10: R17.2@4350,481.5 C16.1@4350,548.5
NetC20_2: C20.2 Q5.4 R30.2 | length 159.5
  Bottom Layer w15: R30.2@3903.62,1900 3961.5,1900 3970,1908.5 3981.5,1920 4053.81,1920 Q5.4@4054.51,1920.7
NetC21_2: C21.2 Q6.4 R31.2 | length 152.3
  Bottom Layer w15: R31.2@3472.13,1038.5 3530,1038.5 3533.5,1042 3562,1042 3587.67,1067.67 Q6.4@3612.3,1067.67
NetC22_2: C22.2 Q7.4 R32.2 | length 421
  Top Layer w15: v1(3995,891.5) 4053.5,950 v1@4285,950
  Bottom Layer w15: R32.2@3953.62,890 3955.12,891.5 v1(3995,891.5) C22.2@4030,891.5 ; Q7.4@4255.49,949.3 4284.3,949.3 v1@4285,950
  other v1: 4290,950
NetC23_1: C23.1 R27.2 | length 57
  Bottom Layer w10: C23.1@4290,1981.5 R27.2@4290,2038.5
NetC24_1: C24.1 R28.2 | length 57
  Bottom Layer w10: C24.1@3847.8,1118.46 R28.2@3847.8,1175.47
NetC25_1: C25.1 R29.2 | length 57
  Bottom Layer w10: R29.2@4350,821.5 C25.1@4350,878.5
NetC34_1: C34.1 R71.1 U3.45 Y1.1 | length 385
  Top Layer w10: U3.45@1960.9,1585.9 1960.9,1770.66 1996.73,1806.5 Y1.1@2003.31,1806.5 ; C34.1@1996.5,1875 1996.5,1813.31 Y1.1@2003.31,1806.5 ; R71.1@2075,1806.5 Y1.1@2003.31,1806.5
NetC35_1: C35.1 U3.46 Y1.3 | length 246.5
  Top Layer w10: C35.1@1840,1748.5 1911.69,1748.5 Y1.3@1916.69,1743.5 1941.2,1719 U3.46@1941.2,1585.9
NetC37_1: C37.1 R47.1 S1.2 U4.3 | length 254.7
  Top Layer w10: C37.1@1090,986.38 U4.3@1141.54,986.38 ; S1.2@1117.32,840 1117.32,907.32 1140,930 R47.1@1166.38,930 1166.38,963.98 U4.3@1142.76,987.6 ; S1.2@1122.32,830 S1.2@1122.32,840
NetC43_1: C43.1 D7.1 L7.1 U6.50 U6.51 | length 180.4
  Top Layer w10: U6.50@3019.92,1630.81 C43.1@3108.24,1630.81 ; U6.51@3019.92,1650.51 C43.1@3112,1650.51
NetC43_2: C43.2 U6.52 | length 104.6
  Top Layer w10: U6.52@3019.92,1670.21 3078.83,1670.21 3109.11,1700.5 C43.2@3112,1700.5
NetC44_1: C44.1 R50.1 | length 57.9
  Top Layer w10: C44.1@2380,1781.38 2383.62,1785 R50.1@2436.38,1785
NetC47_1: C47.1 U6.48 | length 419
  Top Layer w10: U6.48@3019.92,1591.41 v1@3211.41,1591.41
  Bottom Layer w10: C47.1@3010,1661.5 3068.5,1661.5 3135,1595 v1(3210,1595)
NetC48_1: C48.1 U6.13 | length 372.3
  Top Layer w10: v1(2615,1510) 2617.61,1512.61 U6.13@2719.92,1512.61
  Bottom Layer w10: v1(2615,1510) 2604,1521 2604,1638 2659,1693 C48.1@2714.91,1693
NetC49_1: C49.1 U6.43 | length 332.1
  Top Layer w10: U6.43@3019.92,1492.91 3167.09,1492.91 v1@3170,1490
  Bottom Layer w10: C49.1@3010,1531.5 3108.5,1531.5 3150,1490 3168,1490 v1(3172,1486)
NetC50_1: C50.1 U6.14 | length 229.1
  Top Layer w10: C50.1@2510,1446.5 2550.5,1487 2624.53,1487 2630.44,1492.91 U6.14@2719.92,1492.91
NetC50_2: C50.2 U6.15 | length 270.2
  Top Layer w10: C50.2@2510,1383.5 2528,1383.5 2545,1400.5 2545,1440 2574,1469 2631.98,1469 2636.19,1473.21 U6.15@2719.92,1473.21
NetC51_1: C51.1 U6.38 | length 338.5
  Top Layer w10: U6.38@3019.92,1394.41 3115.96,1394.41 3156.37,1354 v1(3166,1354)
  Bottom Layer w10: C51.1@3010,1401.5 3108.5,1401.5 3156,1354 v1(3166,1354)
NetC52_1: C52.1 C53.1 U6.23 | length 190.7
  Top Layer w10: U6.23@2719.92,1315.61 2763.61,1315.61 v1(2782,1334)
  Bottom Layer w10: v1(2782,1334) 2822.5,1334 C53.1@2840.5,1316 C52.1@2840.5,1261
NetC55_1: C55.1 C56.1 U6.27 | length 196.9
  Top Layer w10: C56.1@2658.5,1090 2658.5,1217.5 2677.83,1236.83 U6.27@2719.92,1236.83
NetD1_1: D1.1 Q1.4 R1.1 | length 607.5
  Bottom Layer w10: R1.1@1488.5,2440 1488.5,2416.5 1510,2395 1611.62,2395 1625,2381.62 1625,2150 1599.51,2124.51 Q1.4@1519.3,2124.51
  Bottom Layer w15: D1.1@1403.31,2440 R1.1@1488.5,2440
NetD8_1: D8.1 R43.2 | length 70.4
  Top Layer w10: D8.1@1605,1365.47 1609.53,1370 R43.2@1673.5,1370
NetF1_1: F1.1 J1.2 J1.3
  other v1: 650,2200 690,2200 730,2200 650,2230 690,2230 730,2230 650,2260 690,2260 730,2260 650,2290 690,2290 730,2290 650,2320 690,2320 730,2320 650,2350 690,2350 730,2350 650,2380 690,2380 730,2380
NetJ4_9: J4.9 R42.1 | length 382
  Top Layer w10: R42.1@1863.5,645 1863.5,571.5 1894.52,540.48 1894.52,451.16 1921.16,424.52 1994.52,424.52 J4.9@2040,470
NetR5_2: R5.2 R6.2 U1.1 | length 330.6
  Top Layer w10: R6.2@906.38,1506.3 906.38,1441.42 R5.2@911.5,1436.3 945,1436.3 960,1421.3 960,1351.3 970.43,1340.87 U1.1@1089.41,1340.87
NetR8_2: R8.2 R11.1 R14.2 U1.2 U8.7 | length 654
  Top Layer w10: U1.2@1140.59,1340.87 1213.07,1340.87 1213.5,1341.3 1213.5,1311.5 1233.7,1291.3 1300,1291.3 1375,1366.3 1375,1514.54 1411.95,1551.5 R8.2@1415,1551.5 ; U8.7@1322.2,1614.09 1405.71,1614.09 1410,1609.8 R8.2@1410,1552.8
NetR9_1: R9.1 R10.1 U8.3 | length 237.4
  Top Layer w10: R9.1@1000,1437.8 1036.5,1437.8 1048.5,1449.8 1048.5,1581.5 1055.5,1588.5 U8.3@1097.8,1588.5
NetR12_1: R12.1 R13.2 U8.6 | length 265.3
  Top Layer w10: R12.1@1276.5,1431.3 1276.5,1496.3 1331.3,1496.3 1370,1535 1370,1569.82 1352.01,1587.81 1352.01,1588.5 U8.6@1322.2,1588.5
NetR37_1: R37.1 R38.1 U2.1 | length 130.2
  Top Layer w10: U2.1@2461.34,782.6 2468.74,790 2533.5,790 R37.1@2533.5,735
NetR43_1: R43.1 U3.9 | length 107.9
  Top Layer w10: R43.1@1736.5,1370 1737.3,1370.8 U3.9@1844.1,1370.8
NetR48_1: R48.1 R51.2 U6.55 | length 223.1
  Top Layer w10: v1(2900,1725) 2904.3,1729.3 U6.55@3019.92,1729.3
  Bottom Layer w10: v1(2900,1725) R51.2@2900,1776.38 R48.1@2950,1776.38
NetR56_2: R56.2 U6.7 | length 244.3
  Top Layer w10: R56.2@2481.5,1645 2530,1645 2544.19,1630.81 U6.7@2719.92,1630.81
NetR60_2: R60.2 U6.12 | length 189
  Top Layer w10: R60.2@2538.62,1515 2580,1515 2598,1533 2719.23,1533 U6.12@2719.92,1532.31
NetR62_1: R62.1 U6.26 | length 874.4
  Top Layer w10: v1(2212.5,1052.5) 2292,1132 2540,1132 2664.51,1256.51 U6.26@2719.92,1256.51
  Bottom Layer w10: R62.1@1980,1073.5 1983.03,1070.47 1983.03,1078.03 2020,1115 2150,1115 v1(2212.5,1052.5)
NetR63_1: R63.1 U6.25 | length 996.9
  Top Layer w10: v1(1930,990) 1935,995 R63.1@1935,1063.5 ; v1(2135,1020) 2135,1025 2260,1150 2531,1150 2657.21,1276.21 U6.25@2719.92,1276.21
  Bottom Layer w10: v1(1930,990) 1942,978 2062.54,978 2104.54,1020 v1(2135,1020)
NetR64_1: R64.1 R66.2 U7.7 | length 176.7
  Top Layer w10: U7.7@3006.3,835 3056.5,835 R66.2@3100,791.5 3103.5,795 R64.1@3103.5,855
NetR66_1: R66.1 R70.2 U7.6 | length 177.1
  Top Layer w10: U7.6@3006.3,785 3030,785 3086.5,728.5 R66.1@3100,728.5 R70.2@3160,728.5
NetR68_1: R68.1 R69.2 U7.5 | length 178.2
  Top Layer w10: R69.2@2936.5,620 R68.1@2936.5,675 2995,675 3006.3,686.3 U7.5@3006.3,735
NetR68_2: R68.2 U7.1 U7.2 | length 371.8
  Top Layer w10: U7.2@2793.7,835 2835,835 2873.5,796.5 ; U7.1@2793.7,885 2850,885 2873.5,861.5 2873.5,796.5 ; R68.2@2873.5,675 2873.5,796.5
NetU3_5: U3.5 U5.3 | length 968.3
  Top Layer w10: v1(1795,1446) 1798.6,1449.6 U3.5@1844.1,1449.6 U3.5@1843.3,1448.8
  Bottom Layer w10: v1@1800,1445 1794,1439 1794,1403.47 1972.47,1225 2100,1225 2180,1145 2495,1145 2517.91,1122.09 U5.3@2517.91,1089.96
NSCS: U3.25 U6.8 | length 952
  Top Layer w10: v1(2150,1585) 2150,1560 2121.8,1531.8 2121.8,1521.8 2078.63,1478.63 2078.63,1361.37 2128.3,1311.7 U3.25@2176.1,1311.7 ; v1(2400,1585) 2426.11,1611.11 U6.8@2719.92,1611.11
  Bottom Layer w10: v1(2150,1585) v1(2400,1585)
OCTW: R52.2 U3.36 U6.5 | length 806.2
  Top Layer w10: U3.36@2176.1,1528.4 2176.1,1708.1 2208,1740 ; R52.2@2248,1741.38 2209.38,1741.38 2208,1740 ; U6.5@2719.92,1670.21 2564.79,1670.21 2530,1705 2325,1705 2290,1740 2208,1740
OUT_PWM: R14.1 U3.41 U8.5 | length 1922
  Top Layer w10: R14.1@1276.5,1341.3 1276.5,1371 1274.5,1373 1202,1373 1168.15,1406.85 1168.15,1515 1195.15,1542 1312,1542 1322.2,1552.2 U8.5@1322.2,1562.91 ; U8.5@1292.09,1562.91 1270,1585 1270,1740 1455,1925 2070,1925 2150,1845 2150,1750 2039.7,1639.7 U3.41@2039.7,1585.9
PWM_IN: J2.3 R4.1 R5.1 | length 375.7
  Top Layer w10: J2.3@550,1490 610,1490 663.7,1436.3 R5.1@848.5,1436.3 ; R4.1@848.5,1376.3 R5.1@848.5,1431.3
PWM_OUT: J2.2 R8.1 | length 1333.8
  Top Layer w10: J2.2@550,1590 490,1530 490,1470 520,1440 610,1440 805,1245 1285,1245 1415,1375 1415,1484.8 R8.1@1410,1489.8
